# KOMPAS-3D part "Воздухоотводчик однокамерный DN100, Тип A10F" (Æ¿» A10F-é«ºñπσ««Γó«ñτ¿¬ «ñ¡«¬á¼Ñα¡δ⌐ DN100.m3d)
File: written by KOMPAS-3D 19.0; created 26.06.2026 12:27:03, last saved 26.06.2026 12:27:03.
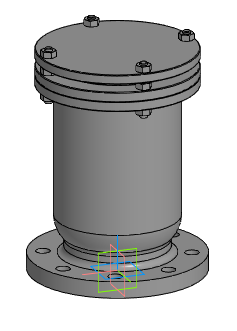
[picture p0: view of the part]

Document properties: Автор: Энергия; Полное имя файла: Z:\3.Личные\kachalov\001_3d для проектировщиков\х.х Тип A10F Воздухоотводчик однокамерный фланцевый\_step\Тип A10F-Воздухоотводчик однокамерный DN100.m3d

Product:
- Part/product: Воздухоотводчик однокамерный DN100  | designation Тип A10F

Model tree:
1. Операция без истории:1  (labels: Тип A10F; Воздухоотводчик однокамерный DN100)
